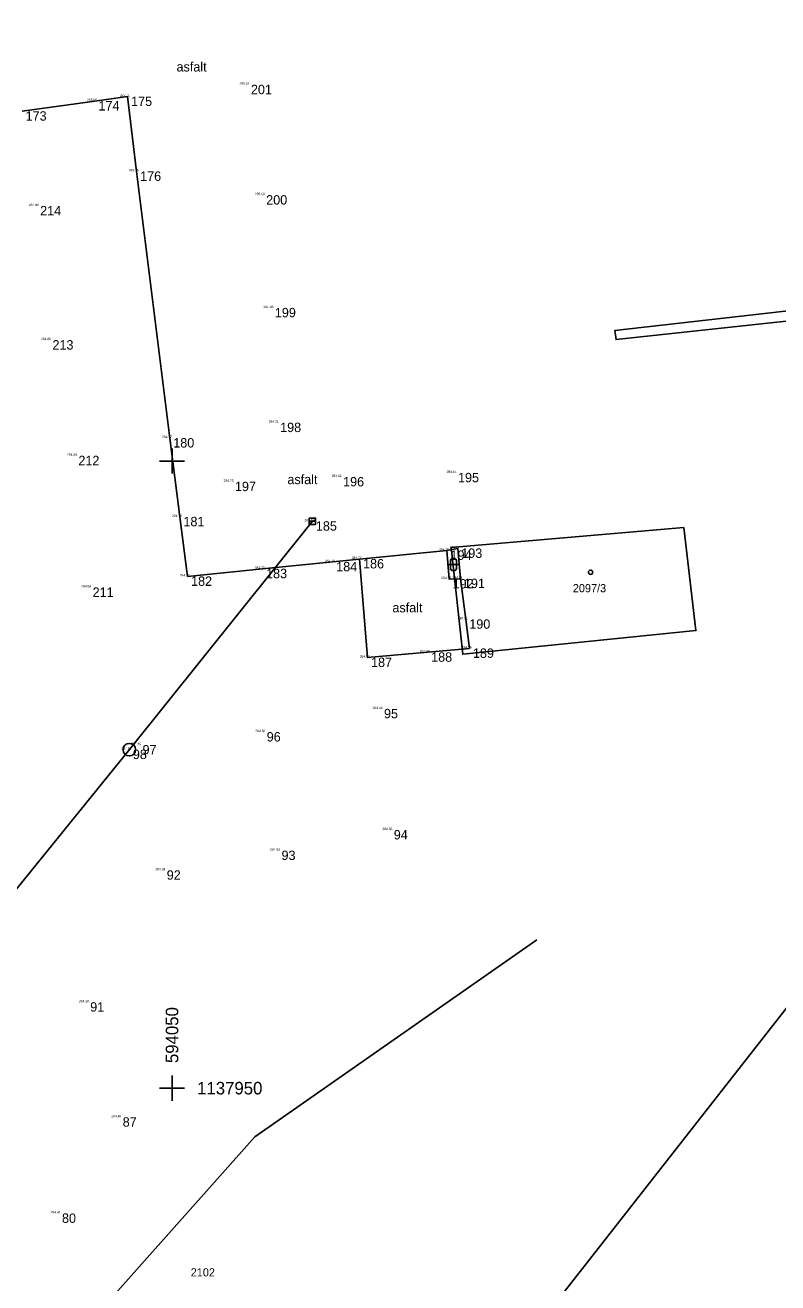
# Model space of a CAD drawing. Extents: x -594197 to -593885, y -1138044 to -1137704.
# Drawn here: x -594061.7 to -594001.7, y -1137965.5 to -1137865.2 of the extents above; entities that cross this region are included whole.
import ezdxf

# ---------------------------------------------------------------- set-up
doc = ezdxf.new("R2010")
doc.units = 0
for name, color, linetype in [('Budovy', 7, 'Continuous'), ('IS kanalizace', 7, 'Continuous'), ('IS neurčené', 7, 'Continuous'), ('Katastrální mapa', 7, 'Continuous'), ('Podrobný bod', 7, 'Continuous'), ('Podrobný bod výška', 7, 'Continuous'), ('Podrobný bod číslo', 7, 'Continuous'), ('Popisy', 7, 'Continuous'), ('Ram mapoveho listu', 7, 'Continuous'), ('Rozhraní ploch', 7, 'Continuous'), ('Vjezdy', 7, 'Continuous'), ('Značky kultur', 7, 'Continuous'), ('Čtvercová síť', 7, 'Continuous')]:
    doc.layers.add(name, color=color, linetype=linetype)

msp = doc.modelspace()

# ---------------------------------------------------------------- linework, layer by layer
at = {"layer": 'Budovy'}
for points in [[(-594027.01, -1137909.38), (-594027.22, -1137906.97)], [(-594026.29, -1137914.94), (-594026.58, -1137912.62)]]:
    msp.add_lwpolyline(points, dxfattribs=at)
at = {"layer": 'IS kanalizace'}
msp.add_lwpolyline([(-594038.81, -1137904.8), (-594053.4, -1137923.01), (-594069.95, -1137943.4), (-594085.67, -1137963.22)], dxfattribs=at)
at = {"layer": 'IS neurčené'}
msp.add_line((-594039.06, -1137904.8), (-594038.56, -1137904.8), dxfattribs=at)
msp.add_lwpolyline([(-594039.06, -1137905.05), (-594038.56, -1137905.05), (-594038.56, -1137904.55), (-594039.06, -1137904.55)], close=True, dxfattribs=at)
msp.add_circle((-594053.4, -1137923.01), 0.5, dxfattribs=at)
at = {"layer": 'Katastrální mapa'}
for points in [[(-593980.59, -1137886.65), (-594014.6, -1137890.31), (-594014.7, -1137889.59), (-593993.88, -1137887.22), (-593994.9, -1137875.4), (-593984.32, -1137874.14), (-593983.5, -1137882.47), (-593976.66, -1137881.62)], [(-594009.21, -1137905.31), (-594008.24, -1137913.52), (-594026.82, -1137915.4), (-594027.76, -1137906.88), (-594009.21, -1137905.31)], [(-594055.62, -1137967.61), (-594043.39, -1137953.89), (-594020.92, -1137938.17)]]:
    msp.add_lwpolyline(points, dxfattribs=at)
msp.add_circle((-594016.63, -1137908.87), 0.175, dxfattribs=at)
at = {"layer": 'Podrobný bod'}
for p, q in [((-594043.99, -1137870), (-594043.99, -1137870)), ((-594056.14, -1137871.3), (-594056.14, -1137871.3)), ((-594053.54, -1137870.94), (-594053.54, -1137870.94)), ((-594052.82, -1137876.91), (-594052.82, -1137876.91)), ((-594042.77, -1137878.8), (-594042.77, -1137878.8)), ((-594060.79, -1137879.66), (-594060.79, -1137879.66)), ((-594042.08, -1137887.79), (-594042.08, -1137887.79)), ((-594059.81, -1137890.36), (-594059.81, -1137890.36)), ((-594041.66, -1137896.94), (-594041.66, -1137896.94)), ((-594050.18, -1137898.17), (-594050.18, -1137898.17)), ((-594057.74, -1137899.58), (-594057.74, -1137899.58)), ((-594027.48, -1137900.94), (-594027.48, -1137900.94)), ((-594045.26, -1137901.65), (-594045.26, -1137901.65)), ((-594036.64, -1137901.27), (-594036.64, -1137901.27)), ((-594049.37, -1137904.45), (-594049.37, -1137904.45)), ((-594038.81, -1137904.8), (-594038.81, -1137904.8)), ((-594035.05, -1137907.81), (-594035.05, -1137907.81)), ((-594028.08, -1137907.13), (-594028.08, -1137907.13)), ((-594027.22, -1137906.97), (-594027.22, -1137906.97)), ((-594042.78, -1137908.59), (-594042.78, -1137908.59)), ((-594037.19, -1137908.04), (-594037.19, -1137908.04)), ((-594048.76, -1137909.2), (-594048.76, -1137909.2)), ((-594027.91, -1137909.41), (-594027.91, -1137909.41)), ((-594027.01, -1137909.38), (-594027.01, -1137909.38)), ((-594056.61, -1137910.08), (-594056.61, -1137910.08)), ((-594026.58, -1137912.62), (-594026.58, -1137912.62)), ((-594026.29, -1137914.94), (-594026.29, -1137914.94)), ((-594034.41, -1137915.67), (-594034.41, -1137915.67)), ((-594029.62, -1137915.25), (-594029.62, -1137915.25)), ((-594033.38, -1137919.76), (-594033.38, -1137919.76)), ((-594042.73, -1137921.61), (-594042.73, -1137921.61)), ((-594053.4, -1137923.01), (-594053.4, -1137923.01)), ((-594052.63, -1137922.64), (-594052.63, -1137922.64)), ((-594032.6, -1137929.42), (-594032.6, -1137929.42)), ((-594041.55, -1137931.06), (-594041.55, -1137931.06)), ((-594050.7, -1137932.63), (-594050.7, -1137932.63)), ((-594056.8, -1137943.15), (-594056.8, -1137943.15)), ((-594054.21, -1137952.32), (-594054.21, -1137952.32)), ((-594059.05, -1137959.99), (-594059.05, -1137959.99))]:
    msp.add_line(p, q, dxfattribs=at)
at = {"layer": 'Ram mapoveho listu'}
msp.add_line((-594079.6, -1138044.01), (-593885.47, -1137795.94), dxfattribs=at)
at = {"layer": 'Rozhraní ploch'}
for points in [[(-594061.95, -1137872.11), (-594056.14, -1137871.3), (-594053.54, -1137870.94), (-594052.82, -1137876.91), (-594050.18, -1137898.17), (-594049.37, -1137904.45), (-594048.76, -1137909.2), (-594042.78, -1137908.59), (-594037.19, -1137908.04), (-594035.05, -1137907.81), (-594034.41, -1137915.67), (-594029.62, -1137915.25), (-594026.29, -1137914.94)], [(-594035.05, -1137907.81), (-594028.08, -1137907.13)], [(-594028.08, -1137907.13), (-594027.22, -1137906.97)], [(-594027.01, -1137909.38), (-594027.91, -1137909.41), (-594028.08, -1137907.13)]]:
    msp.add_lwpolyline(points, dxfattribs=at)
at = {"layer": 'Vjezdy'}
msp.add_lwpolyline([(-594026.58, -1137912.62), (-594027.01, -1137909.38)], dxfattribs=at)
at = {"layer": 'Značky kultur'}
for p, q in [((-594028.06, -1137908.24), (-594027.06, -1137908.24)), ((-594027.81, -1137908.49), (-594027.81, -1137907.99)), ((-594027.31, -1137908.49), (-594027.31, -1137907.99))]:
    msp.add_line(p, q, dxfattribs=at)
for centre, start, end in [((-594027.56, -1137907.99), 0, 180), ((-594027.56, -1137908.49), 180, 360)]:
    msp.add_arc(centre, 0.25, start, end, dxfattribs=at)
at = {"layer": 'Čtvercová síť'}
for p, q in [((-594050, -1137901), (-594050, -1137899)), ((-594051, -1137900), (-594049, -1137900)), ((-594050, -1137951), (-594050, -1137949)), ((-594051, -1137950), (-594049, -1137950))]:
    msp.add_line(p, q, dxfattribs=at)

# ---------------------------------------------------------------- texts
at = {"layer": 'Katastrální mapa'}
for s, p in [('2097/3', (-594018.05, -1137910.46)), ('2102', (-594048.51, -1137965.01))]:
    msp.add_text(s, height=0.65, dxfattribs=at).set_placement(p)
at = {"layer": 'Podrobný bod výška'}
for s, p in [('285.01 ', (-594044.62, -1137870)), ('285.11 ', (-594054.17, -1137870.94)), ('285.05 ', (-594056.77, -1137871.3)), ('285.15 ', (-594053.45, -1137876.91)), ('285.08 ', (-594043.4, -1137878.8)), ('284.80 ', (-594061.42, -1137879.66)), ('284.88 ', (-594042.71, -1137887.79)), ('284.68 ', (-594060.44, -1137890.36)), ('284.71 ', (-594042.29, -1137896.94)), ('284.77 ', (-594050.81, -1137898.17)), ('284.64 ', (-594058.37, -1137899.58)), ('284.64 ', (-594028.11, -1137900.94)), ('284.73 ', (-594045.89, -1137901.65)), ('284.61 ', (-594037.27, -1137901.27)), ('284.78 ', (-594050, -1137904.45)), ('284.59 ', (-594039.44, -1137904.8)), ('284.75 ', (-594028.71, -1137907.13)), ('284.82 ', (-594027.85, -1137906.97)), ('284.70 ', (-594037.82, -1137908.04)), ('284.70 ', (-594035.68, -1137907.81)), ('284.73 ', (-594043.41, -1137908.59)), ('284.56 ', (-594057.24, -1137910.08)), ('284.77 ', (-594049.39, -1137909.2)), ('284.77 ', (-594028.54, -1137909.41)), ('284.84 ', (-594027.64, -1137909.38)), ('284.81 ', (-594027.21, -1137912.62)), ('284.75 ', (-594026.92, -1137914.94)), ('284.60 ', (-594035.04, -1137915.67)), ('284.69 ', (-594030.25, -1137915.25)), ('284.56 ', (-594034.01, -1137919.76)), ('284.50 ', (-594043.36, -1137921.61)), ('284.52 ', (-594054.03, -1137923.01)), ('284.45 ', (-594053.26, -1137922.64)), ('284.56 ', (-594033.23, -1137929.42)), ('284.53 ', (-594042.18, -1137931.06)), ('284.33 ', (-594051.33, -1137932.63)), ('284.38 ', (-594057.43, -1137943.15)), ('284.48 ', (-594054.84, -1137952.32)), ('284.41 ', (-594059.68, -1137959.99))]:
    msp.add_text(s, height=0.188, dxfattribs=at).set_placement(p)
at = {"layer": 'Podrobný bod číslo'}
for s, p in [(' 201', (-594043.99, -1137870.75)), (' 174', (-594056.14, -1137872.05)), (' 175', (-594053.54, -1137871.69)), (' 173', (-594061.95, -1137872.86)), (' 176', (-594052.82, -1137877.66)), (' 200', (-594042.77, -1137879.55)), (' 214', (-594060.79, -1137880.41)), (' 199', (-594042.08, -1137888.54)), (' 213', (-594059.81, -1137891.11)), (' 198', (-594041.66, -1137897.69)), (' 180', (-594050.18, -1137898.92)), (' 212', (-594057.74, -1137900.33)), (' 195', (-594027.48, -1137901.69)), (' 197', (-594045.26, -1137902.4)), (' 196', (-594036.64, -1137902.02)), (' 181', (-594049.37, -1137905.2)), (' 185', (-594038.81, -1137905.55)), (' 193', (-594027.22, -1137907.72)), (' 186', (-594035.05, -1137908.56)), (' 194', (-594028.08, -1137907.88)), (' 183', (-594042.78, -1137909.34)), (' 184', (-594037.19, -1137908.79)), (' 182', (-594048.76, -1137909.95)), (' 192', (-594027.91, -1137910.16)), (' 191', (-594027.01, -1137910.13)), (' 211', (-594056.61, -1137910.83)), (' 190', (-594026.58, -1137913.37)), (' 189', (-594026.29, -1137915.69)), (' 187', (-594034.41, -1137916.42)), (' 188', (-594029.62, -1137916)), (' 95', (-594033.38, -1137920.51)), (' 96', (-594042.73, -1137922.36)), (' 98', (-594053.4, -1137923.76)), (' 97', (-594052.63, -1137923.39)), (' 94', (-594032.6, -1137930.17)), (' 93', (-594041.55, -1137931.81)), (' 92', (-594050.7, -1137933.38)), (' 91', (-594056.8, -1137943.9)), (' 87', (-594054.21, -1137953.07)), (' 80', (-594059.05, -1137960.74))]:
    msp.add_text(s, height=0.75, dxfattribs=at).set_placement(p)
at = {"layer": 'Popisy'}
for p in [(-594049.64, -1137868.94), (-594040.8, -1137901.84), (-594032.43, -1137912.06)]:
    msp.add_text('asfalt', height=0.75, dxfattribs=at).set_placement(p)
at = {"layer": 'Čtvercová síť'}
msp.add_text('594050', height=1, rotation=90, dxfattribs=at).set_placement((-594049.5, -1137948))
msp.add_text('1137950', height=1, dxfattribs=at).set_placement((-594048, -1137950.5))

doc.saveas('drawing.dxf')
